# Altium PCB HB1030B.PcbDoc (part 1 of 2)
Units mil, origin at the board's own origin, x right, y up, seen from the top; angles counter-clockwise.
Board outline 1259.84 x 2086.61 mil, 2 copper layers (Top Layer, Bottom Layer); 36 components, 40 nets, 161 pads, 288 vias.
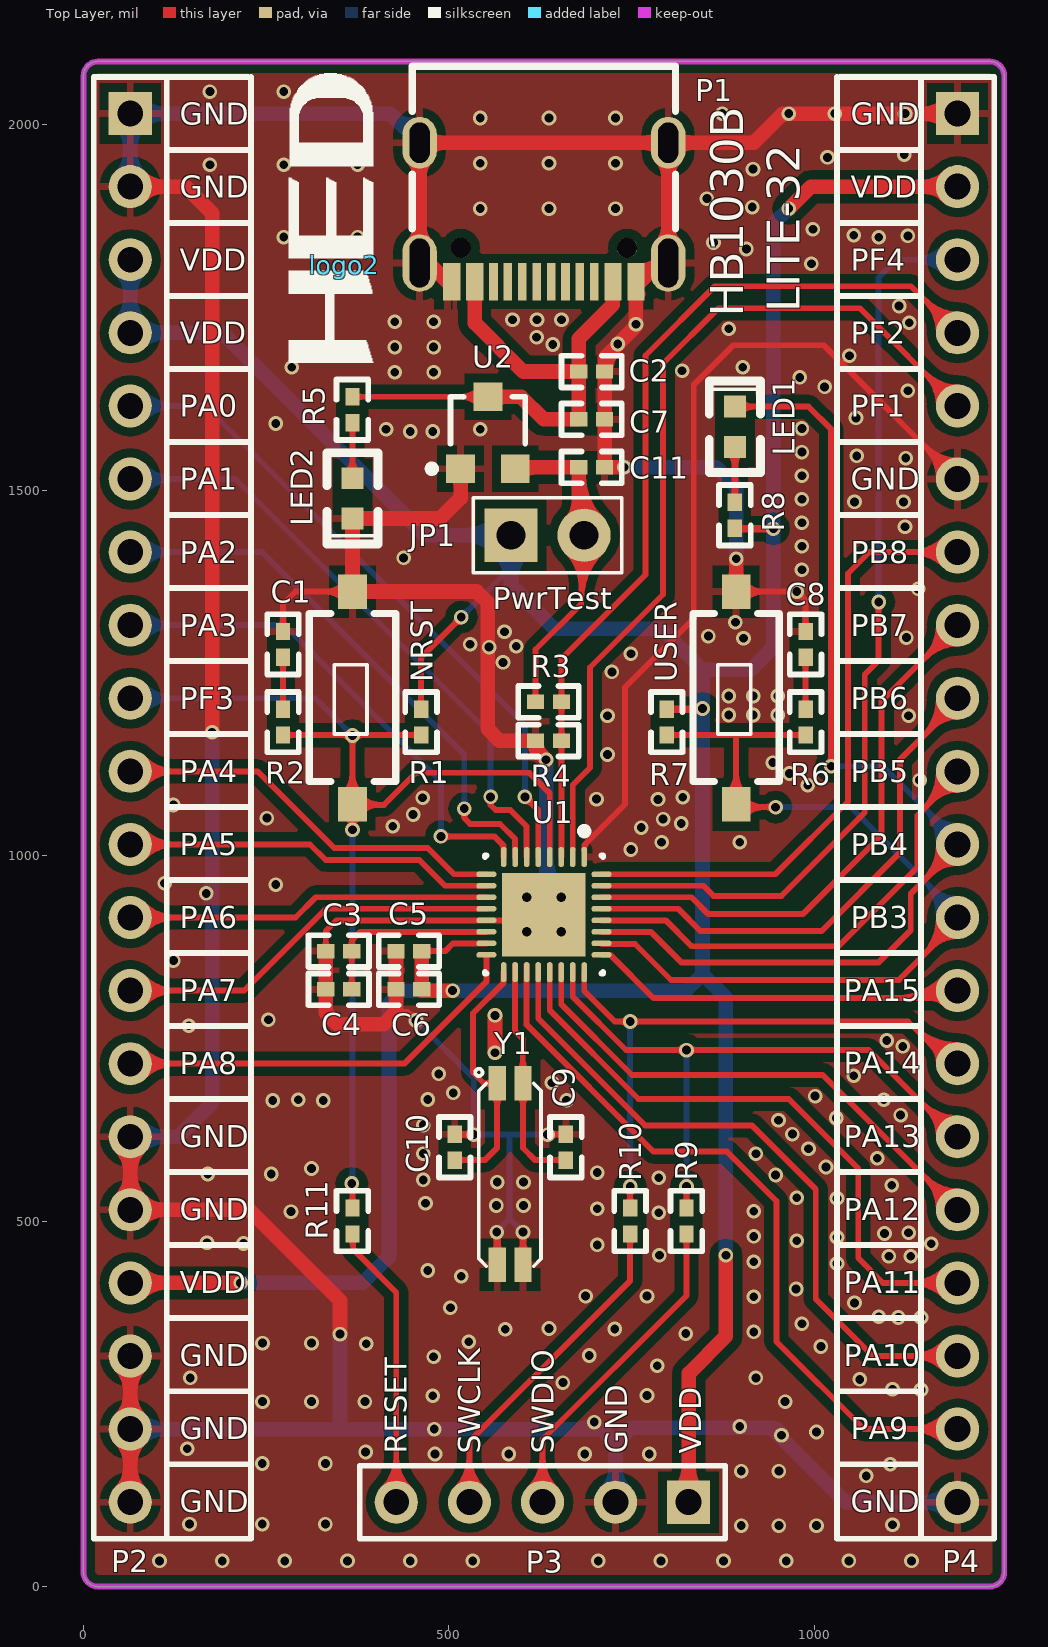
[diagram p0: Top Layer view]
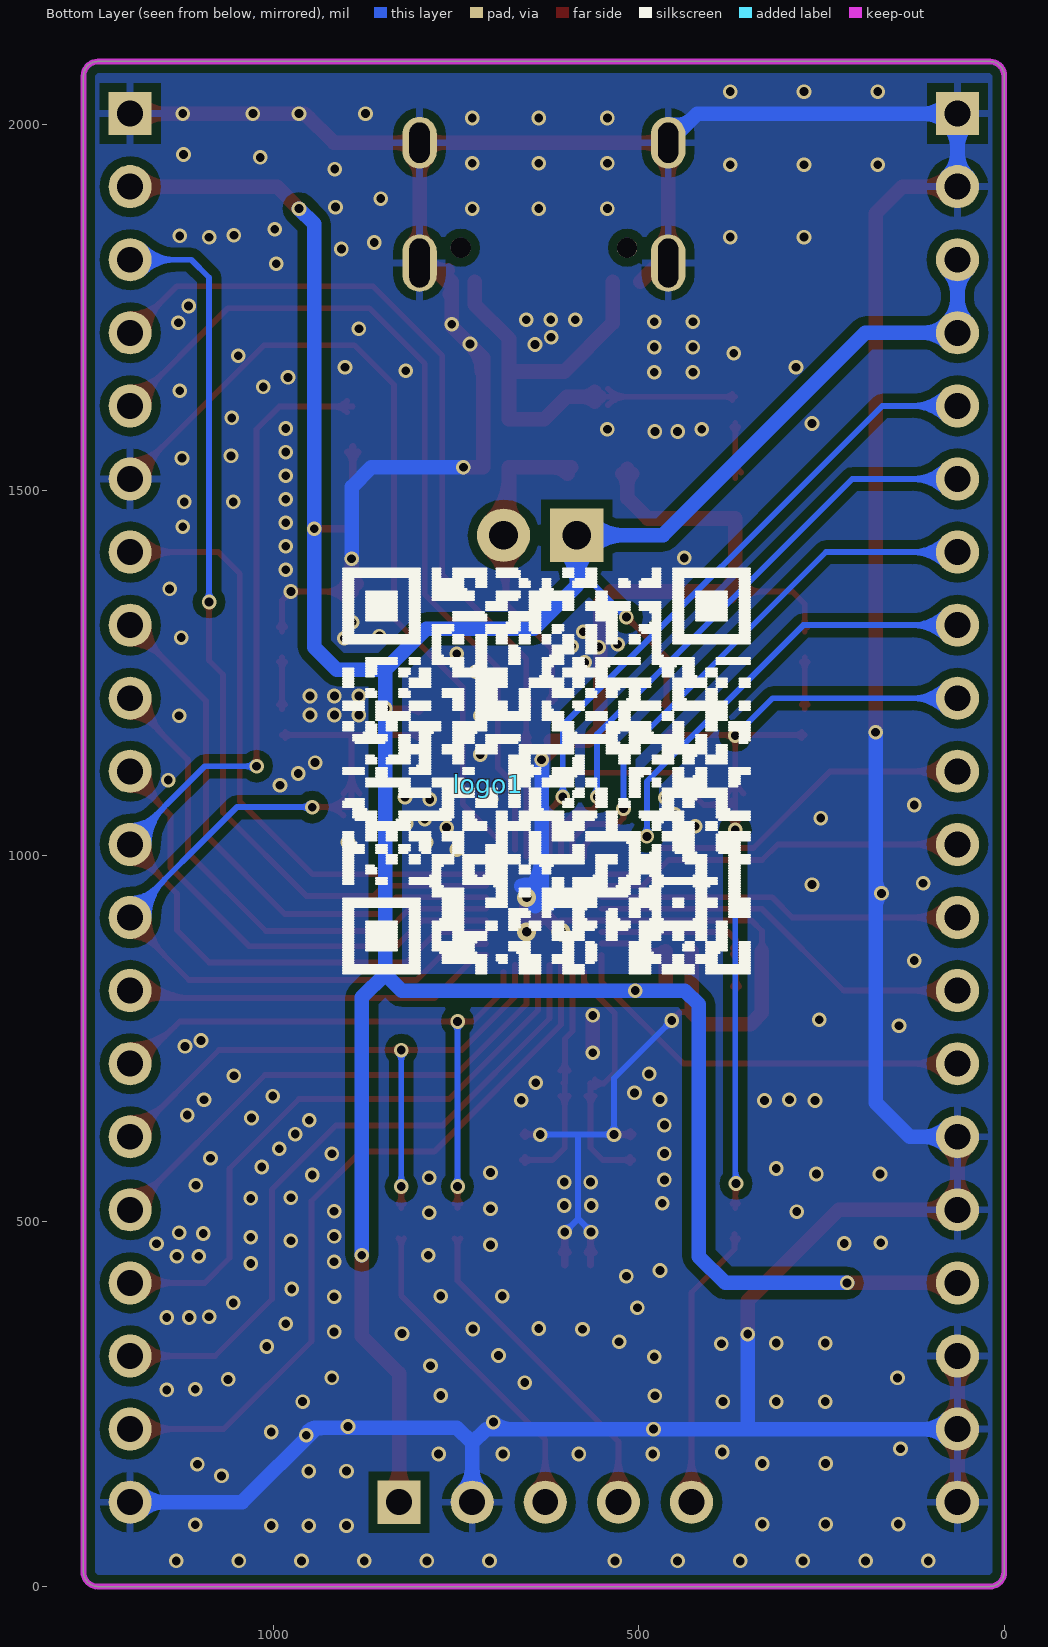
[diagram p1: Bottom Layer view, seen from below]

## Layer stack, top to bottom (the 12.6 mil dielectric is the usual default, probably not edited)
Top Layer: signal copper 1.4
Dielectric: dielectric 12.6, FR-4, Dk 4.8
Bottom Layer: signal copper 1.4

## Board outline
0,19.68 0,2066.93 cw(c19.69,2066.93) 19.69,2086.61 1240.16,2086.61 cw(c1240.16,2066.93) 1259.84,2066.93 1259.84,19.68 cw(c1240.16,19.68) 1240.16,0 19.69,0 cw(c19.69,19.68)

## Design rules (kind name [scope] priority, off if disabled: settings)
Clearance [(IsPad and InComponent('U1'))] p1: gap=7
Clearance Clearance_poly [(InPolygon)] p2: gap=12
Clearance Clearance_CN [(IsPad and InComponent('P1'))] p3: gap=7
Clearance Clearance_Pad [All] p4: gap=7
ComponentClearance [All] p1: gap=0 collisioncheckmode=3 verticalgap=0 showdistances=FALSE
HoleSize [All] p1: absolutevalues=TRUE maxlimit=130 minlimit=1 maxpercent=80.000 minpercent=20.000
MinimumSolderMaskSliver [All] p1: minsoldermaskwidth=0
PolygonConnect PolygonConnect_Pads [IsPad] p1: connectstyle=Relief reliefconductorwidth=10 reliefentries=4 polygonreliefangle="90 Angle"
PolygonConnect [All] p2: connectstyle=Direct reliefconductorwidth=10 reliefentries=4 polygonreliefangle="90 Angle"
RoutingVias [All] p1: holewidth=12 width=20 viastyle="Through Hole" minholewidth=10 minwidth=18 maxholewidth=300 maxwidth=500
SilkToSilkClearance [All] p1: silktosilkclearance=0
SilkscreenOverComponentPads [IsPad] p1: minsilkscreentomaskgap=0
SolderMaskExpansion [All] p1: expansion=4
TestPointUsage [All] p1: valid=0 allowmultiple=FALSE
Testpoint [(IsPad And (OnTopLayer Or OnBottomLayer))] p1: side=3 testpointundercomponent=TRUE minsize=40 maxsize=100 preferedsize=60 minholesize=0 maxholesize=40 preferedholesize=32 testpointgrid=1 style=297 order=0123456789
Width [All] p1: maxlimit=20 minlimit=8 preferedwidth=8
19 further rules are at their usual default settings.

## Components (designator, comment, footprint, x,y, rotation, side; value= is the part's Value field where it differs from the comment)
C1 "0.1u" 0402 273,1271.37 r90 top
C2 "0.1u" 0402 713,1662.37 r180 top
C3 "0.1u" 0402 367,869.37 r180 top
C4 "1u" 0402 367,816.97 r180 top
C5 "0.1u" 0402 427.57,869.37 r0 top
C6 "4.7u" 0402 427.57,816.97 r0 top
C7 "10u" 0402 713,1596.87 r180 top
C8 "0.1u" 0402 988,1306.81 r270 top
C9 "10p" 0402 660,618.81 r270 top
C10 "10p" 0402 508,618.81 r270 top
C11 "10u" 0402 713,1531.28 r180 top
JP1 "Header 1x2" HEADER_1X2_2.54 635,1438.37 r0 top (schematic designator JP2)
LED1 "LED_G" 0603-P 891.35,1559.37 r90 top
LED2 "LED_R" 0603-P 368,1516.37 r270 top
logo1 "SIGN" SIGN 706,1098.37 r180 bottom
logo2 "logo" LOGO 357,1808.37 r90 top
NRST "TS-1101-C-W" 按键_TS-1101-C-W 368,1361.37 r270 top locked
P1 "TYPE-C-16P" HED-KH-TYPE-C-16P 800,1810.82 r0 top locked
P2 "Header 20" HDR1X20 64,2015.37 r270 top locked
P3 "Header 1x5" HDR1X5_2.54 828,115.37 r180 top locked
P4 "Header 20" HDR1X20 1196,2015.37 r270 top locked
R1 "10k" 0402 462,1200.37 r270 top
R2 "10R" 0402 273,1164.94 r90 top
R3 "20K" 0402 654,1210.37 r180 top
R4 "10K" 0402 654,1157.37 r180 top
R5 "1K" 0402 368,1592.37 r90 top
R6 "10R" 0402 988,1200.37 r270 top
R7 "4.7k" 0402 798,1164.94 r90 top
R8 "510R" 0402 891.35,1483.37 r270 top
R9 "470R" 0402 825,517.81 r270 top
R10 "470R" 0402 748,517.81 r270 top
R11 "470R" 0402 368,517.81 r270 top
U1 "CIU32L030K8U6" CIU32L030-QFN32 630,919.37 r270 top locked
U2 "ME6210A33M3G" SOT-23-3 551,1574.37 r0 top locked
USER "TS-1101-C-W" 按键_TS-1101-C-W 893,1361.37 r270 top locked
Y1 "M6-32.768KHz 12.5pF" XTAL-MC146 566,688.37 r270 top

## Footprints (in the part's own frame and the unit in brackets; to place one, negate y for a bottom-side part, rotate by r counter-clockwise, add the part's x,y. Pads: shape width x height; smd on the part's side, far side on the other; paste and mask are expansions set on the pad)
0402 [mm]
  rect 0.6x0.5 smd: 1(0,0) 2(0.9,0)
  silkscreen extent -0.6,-0.55 1.5,0.55
0603-P [mil]
  rect 30x30 smd: 1(0,0) 2(55,0)
  silkscreen extent -35,-35 90,35, body extent 1,-15 60,15, height 10
CIU32L030-QFN32 [mm] "QFN, 32-Leads, Body 4.1x4.1mm (max), Pitch 0.40mm, IPC Medium Density"
  oval 0.7x0.2 smd: 1(-2,1.4) 2(-2,1) 3(-2,0.6) 4(-2,0.2) 5(-2,-0.2) 6(-2,-0.6) 7(-2,-1) 8(-2,-1.4) 17(2,-1.4) 18(2,-1) 19(2,-0.6) 20(2,-0.2) 21(2,0.2) 22(2,0.6) 23(2,1) 24(2,1.4)
  oval 0.2x0.7 smd: 9(-1.4,-2) 10(-1,-2) 11(-0.6,-2) 12(-0.2,-2) 13(0.2,-2) 14(0.6,-2) 15(1,-2) 16(1.4,-2) 25(1.4,2) 26(1,2) 27(0.6,2) 28(0.2,2) 29(-0.2,2) 30(-0.6,2) 31(-1,2) 32(-1.4,2)
  rect 2.9x2.9 smd: 33(0,0)
  silkscreen extent -3.02,-2.05 2.05,2.05, body extent -2.05,-2.05 2.05,2.05, height 0.8
HDR1X5_2.54 [mm]
  rect 1.5x1.5 hole 0.9: 1(0,0)
  round 1.5 hole 0.9: 2(2.54,0) 3(5.08,0) 4(7.62,0) 5(10.16,0)
  silkscreen extent -1.27,-1.27 11.43,1.27
HDR1X20 [mm] "Connector; Header; 20 Position"
  rect 1.5x1.5 hole 0.9: 1(0,0)
  round 1.5 hole 0.9: 2(2.54,0) 3(5.08,0) 4(7.62,0) 5(10.16,0) 6(12.7,0) 7(15.24,0) 8(17.78,0) 9(20.32,0) 10(22.86,0) 11(25.4,0) 12(27.94,0) 13(30.48,0) 14(33.02,0) 15(35.56,0) 16(38.1,0) 17(40.64,0) 18(43.18,0) 19(45.72,0) 20(48.26,0)
  silkscreen extent -1.27,-1.27 49.53,1.27
HEADER_1X2_2.54 [mm]
  rect 1.85x1.85 / inner round 1.85 / far side rect 1.85x1.85 hole 1: 1(-1.27,0)
  round 1.85 hole 1: 2(1.27,0)
  silkscreen extent -2.58,-1.3 2.58,1.3, body extent -2.67,-1.3 2.58,1.3, height 8.38
HED-KH-TYPE-C-16P [mm]
  oval 1.2x2 hole 0.7 slot 1.7 at 90 deg: 1(0,0) 2(-8.64,0)
  oval 1.2x1.8 hole 0.7 slot 1.4 at 90 deg: 3(0,4.18) 4(-8.64,4.18)
  rect 0.3x1.3 smd: A1(-0.97,-0.65) A4(-1.77,-0.65) A5(-3.07,-0.65) A6(-4.07,-0.65) A7(-4.57,-0.65) A8(-5.57,-0.65) A9(-6.87,-0.65) A12(-7.67,-0.65) B1(-7.37,-0.65) B4(-6.57,-0.65) B5(-6.07,-0.65) B6(-5.07,-0.65) B7(-3.57,-0.65) B8(-2.57,-0.65) B9(-2.07,-0.65) B12(-1.27,-0.65)
  round 0.7 hole 0.7 unplated: ""(-7.21,0.53) ""(-1.43,0.53)
  silkscreen extent -8.89,1.19 0.25,6.84
LOGO [mil]
  silkscreen extent -134,-39 262,75
SIGN [mil]
  silkscreen extent -199,-259 358,294
SOT-23-3 [mm]
  rect 1x1 smd: 1(-0.889,-1.143) 2(1.011,-1.143) 3(0.061,1.357)
  silkscreen extent -2.01,-1.27 1.36,1.36, body extent -1.39,-1.29 1.51,1.51, height 1.2
XTAL-MC146 [mm]
  rect 1.2x0.6 smd mask+0.05: 1(0,0) 2(6.3,0) 3(6.3,0.9) 4(0,0.9)
  silkscreen extent -0.51,-0.76 6.35,1.52
按键_TS-1101-C-W [mm] "星坤品牌"
  rect 1.2x1 smd mask+0.05: 1(0,0) 2(7.4,0)
  silkscreen extent 0.76,-1.5 6.6,1.5

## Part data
C1 C3 C4 C5 C6: library part MCD-00211, "Capacitor, MLCC, 100nF, 16V, X7R, 10%, 0603, T=0,8mm"
C2: library part "0603 100nF 10% 50V", "贴片电容"
C7 C11: library part MCD-00014, "Capacitor, MLCC, 10uF, 25V, X5R, 10%, 0805, T=0,85mm"
C8: library part MCD-00211, "贴片电容"
C9 C10: library part Capacitor, "Capacitor, MLCC, 100nF, 16V, X7R, 10%, 0603, T=0,8mm"
JP1: library part MCD-00683, "Header, 2x1, 2,54mm, VR, TH, Height 5.84mm/2.54mm - Shunt Fitted by default"
LED1: library part LED1, "贴片LED 绿色"
LED2: library part LED1, "贴片LED 红色"
NRST: library part SW-PB, "Switch"
P1: library part KH-TYPE-C-16P, "TYPE-C USB接口"
P2 P4: "Header, 20-Pin"
P3: library part SWD, "Header, 1x5, 2,54mm, VR, TH, Height 5.84mm/2.54mm"
R1 R2 R3 R4 R5 R6 R7 R8 R9 R10 R11: library part Res2, "贴片电阻"
U2: library part ME6210, "贴片LDO3.3V"
USER: library part SW-PB, "贴片按键"
Y1: library part MC146, "贴片晶振"

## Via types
v1: diameter 20, hole 12, Top Layer to Bottom Layer, tented both sides, 284 vias
v2: diameter 25.98, hole 12.99, Top Layer to Bottom Layer, tented top, 4 vias

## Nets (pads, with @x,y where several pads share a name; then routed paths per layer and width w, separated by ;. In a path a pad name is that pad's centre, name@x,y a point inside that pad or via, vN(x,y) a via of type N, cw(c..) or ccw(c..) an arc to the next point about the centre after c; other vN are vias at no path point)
GND: C1.2 C2.1 C3.2 C4.2 C5.1 C6.1 C7.1 C8.1 C9.1 C10.1 C11.1 LED2.2 NRST.1 P1.1 P1.2 P1.3 P1.4 P1.A1 P1.A12 P1.B1 P1.B12 P2.1 P2.2 P2.15 P2.16 P2.18 P2.19 P2.20 P3.2 P4.1 P4.6 P4.20 R4.2 U1.1 U1.13 U1.33 U2.1 USER.1 Y1.2 Y1.3 | length 16114.8
  Top Layer w8: C1.2@273,1306.81 273,1344.37 290,1361.37 NRST.1@368,1361.37 ; C3.2@331.57,869.37 331.57,896.94 346.13,911.5 U1.13@551.26,911.5 U1.33@606.38,911.5 ; C6.1@427,815.37 C6.1@427.57,815.94 ; 427.57,785.94 443.43,785.94 v1(455,774.37) ; R4.2@618.57,1155.6 R4.2@618.57,1157.37 ; U1.33@622.13,921.5 U1.33@630,929.37 ; v1(635,618.37) C9.1@659.57,618.37 ; U1.1@685.12,1008.11 685.12,1014.49 741,1070.37 741,1230.37 835,1324.37 835,1644.37 889,1698.37 1013,1698.37 P4.6@1196,1515.37 ; USER.1@893,1361.37 v1(976,1361.37) 988,1349.37 C8.1@988,1306.81 ; 273,1322.88 cw(c258.9,1322.88) 268.87,1312.91 ccw(c258.9,1322.88) 273,1322.88 ; 273,1322.88 ccw(c287.1,1322.88) 277.13,1312.91 cw(c287.1,1322.88) 273,1322.88 ; 330.13,1361.37 cw(c330.13,1323.51) 356.91,1350.28 ccw(c330.13,1323.51) 330.13,1361.37 ; 330.13,1361.37 ccw(c330.13,1399.24) 356.91,1372.46 cw(c330.13,1399.24) 330.13,1361.37 ; 331.57,883.48 cw(c317.46,883.48) 327.44,873.51 ccw(c317.46,883.48) 331.57,883.48 ; 331.57,883.48 ccw(c345.67,883.48) 335.7,873.51 cw(c345.67,883.48) 331.57,883.48 ; 444.76,784.62 cw(c434.51,774.37) 449,774.37 ccw(c434.51,774.37) 444.76,784.62 ; 444.76,784.62 ccw(c455,794.86) 455,780.37 cw(c455,794.86) 444.76,784.62 ; 649.49,618.37 cw(c649.49,632.86) 639.24,622.62 ccw(c649.49,632.86) 649.49,618.37 ; 649.49,618.37 ccw(c649.49,603.89) 639.24,614.13 cw(c649.49,603.89) 649.49,618.37 ; 930.87,1361.37 cw(c930.87,1399.24) 904.09,1372.46 ccw(c930.87,1399.24) 930.87,1361.37 ; 930.87,1361.37 ccw(c930.87,1323.51) 904.09,1350.28 cw(c930.87,1323.51) 930.87,1361.37 ; 961.51,1361.37 cw(c961.51,1346.89) 971.76,1357.13 ccw(c961.51,1346.89) 961.51,1361.37 ; 961.51,1361.37 ccw(c961.51,1375.86) 971.76,1365.62 cw(c961.51,1375.86) 961.51,1361.37 ; 986.24,1351.13 cw(c996.49,1361.37) 982,1361.37 ccw(c996.49,1361.37) 986.24,1351.13 ; 986.24,1351.13 ccw(c976,1340.89) 976,1355.37 cw(c976,1340.89) 986.24,1351.13 ; 988,1322.88 cw(c973.9,1322.88) 983.87,1312.91 ccw(c973.9,1322.88) 988,1322.88 ; 988,1322.88 ccw(c1002.1,1322.88) 992.13,1312.91 cw(c1002.1,1322.88) 988,1322.88 ; 1152.42,1558.95 cw(c1108.84,1515.37) 1170.47,1515.37 ccw(c1108.84,1515.37) 1152.42,1558.95 ; 1152.42,1558.95 ccw(c1196,1602.53) 1196,1540.9 cw(c1196,1602.53) 1152.42,1558.95 ; 1166.08,1545.3 cw(c1136.16,1515.37) 1178.47,1515.37 ccw(c1136.16,1515.37) 1166.08,1545.3 ; 1166.08,1545.3 ccw(c1196,1575.22) 1196,1532.9 cw(c1196,1575.22) 1166.08,1545.3 ; v1@644.85,618.37 ccw(c644.85,633.96) 655.87,622.94 cw(c644.85,633.96) v1@644.85,618.37 ; 646.94,618.37 cw(c646.94,605.75) 655.87,614.68 ccw(c646.94,605.75) 646.94,618.37 ; U1.1@685.06,1007.96 cw(c700.68,1007.96) 689.63,1019.01 ccw(c700.68,1007.96) U1.1@685.06,1007.96
  Top Layer w10: P2.15@59,615.37 P2.15@64,615.37 ; P1.2@451.45,1810.82 P1.2@459.84,1810.82 ; C10.1@508,618.81 508.43,618.37 v1(534,618.37) ; v1(565.43,484.94) 566,484.37 Y1.2@566,440.34 ; Y1.3@601.43,440.34 v1(601.43,484.94) ; v1@635,619.37 v1@635.57,618.81 ; 521.93,618.37 cw(c521.93,606.3) 530.46,614.84 ccw(c521.93,606.3) 521.93,618.37 ; 521.93,618.37 ccw(c521.93,630.45) 530.46,621.91 cw(c521.93,630.45) 521.93,618.37 ; 566,468.6 cw(c549.56,468.6) 561.18,456.97 ccw(c549.56,468.6) 566,468.6 ; 566,468.6 ccw(c582.44,468.6) 570.82,456.97 cw(c582.44,468.6) 566,468.6 ; 601.43,468.6 cw(c584.99,468.6) 596.62,456.97 ccw(c584.99,468.6) 601.43,468.6 ; 601.43,468.6 ccw(c617.88,468.6) 606.25,456.97 cw(c617.88,468.6) 601.43,468.6 ; 601.43,472.87 cw(c613.5,472.87) 604.97,481.41 ccw(c613.5,472.87) 601.43,472.87 ; 601.43,472.87 ccw(c589.36,472.87) 597.9,481.41 cw(c589.36,472.87) 601.43,472.87 ; C10.1@511.42,615.38 cw(c518.65,608.16) 518.65,618.37 ccw(c518.65,608.16) C10.1@511.42,615.38 ; C10.1@511.42,622.23 ccw(c520.74,631.54) 520.74,618.37 cw(c520.74,631.54) C10.1@511.42,622.23 ; v1@561.9,481.41 cw(c551.99,471.5) 566,471.5 ccw(c551.99,471.5) v1@561.9,481.41 ; 566,474.24 cw(c576.14,474.24) 568.97,481.41 ccw(c576.14,474.24) 566,474.24
  Top Layer w20: P2.20@64,115.37 P2.19@64,215.37 P2.18@64,315.37 ; P2.15@64,615.37 P2.16@64,515.37 226.63,515.37 351,391 v1(351,345.37) ; P2.2@64,1915.37 139.63,1915.37 176,1879 v1(176,1169) ; C3.2@331.57,869.37 C4.2@331.57,816.97 331.57,784.81 347,769.37 411,769.37 427.57,785.94 C6.1@427.57,815.94 ; C6.1@427.57,816.97 C5.1@427.57,869.37 ; P1.A12@498.03,1785.23 472.43,1810.82 P1.2@459.84,1810.82 P1.4@459.84,1975.39 P1.3@800,1975.39 ; U2.1@516,1529.37 516,1489.37 488,1461.37 LED2.2@368,1461.37 NRST.1@368,1361.37 538,1361.37 553,1346.37 553,1173.37 569,1157.37 R4.2@618.57,1157.37 618.57,1145.81 v1(633,1131.37) ; v1(563,730.37) v1(563,781.37) ; v2(606.38,895.75) v2(653.62,943) v2(653.62,895.75) U1.33@630,919.37 ; C11.1@713,1531.28 C7.1@713,1596.87 C2.1@713,1662.37 713,1681.37 755.81,1724.19 P1.B12@755.81,1785.23 ; C11.1@713.09,1531.37 v1(740,1531.37) ; P1.A1@761.81,1785.23 P1.1@787.41,1810.82 ; USER.1@893,1361.37 v1(893,1406.37) ; P4.1@1196,2015.37 957,2015.37 917.02,1975.39 P1.3@800,1975.39 ; 64,162.52 cw(c16.86,162.52) 50.19,129.18 ccw(c16.86,162.52) 64,162.52 ; 64,162.52 ccw(c111.14,162.52) 77.81,129.18 cw(c111.14,162.52) 64,162.52 ; 64,168.23 cw(c111.14,168.23) 77.81,201.57 ccw(c111.14,168.23) 64,168.23 ; 64,168.23 ccw(c16.86,168.23) 50.19,201.57 cw(c16.86,168.23) 64,168.23 ; 64,262.52 cw(c16.86,262.52) 50.19,229.18 ccw(c16.86,262.52) 64,262.52 ; 64,262.52 ccw(c111.14,262.52) 77.81,229.18 cw(c111.14,262.52) 64,262.52 ; 64,268.23 cw(c111.14,268.23) 77.81,301.57 ccw(c111.14,268.23) 64,268.23 ; 64,268.23 ccw(c16.86,268.23) 50.19,301.57 cw(c16.86,268.23) 64,268.23 ; 64,562.52 cw(c16.86,562.52) 50.19,529.18 ccw(c16.86,562.52) 64,562.52 ; 64,562.52 ccw(c111.14,562.52) P2.16@77.81,529.18 ; 64,562.52 ccw(c111.14,562.52) P2.16@77.81,529.18 ; 64,568.23 cw(c111.14,568.23) 77.81,601.57 ccw(c111.14,568.23) 64,568.23 ; 64,568.23 ccw(c16.86,568.23) 50.19,601.57 cw(c16.86,568.23) 64,568.23 ; P2.16@77.81,529.18 ccw(c111.14,562.52) 111.14,515.37 ; P2.16@77.81,529.18 ccw(c111.14,562.52) 111.14,515.37 ; 111.14,515.37 ccw(c111.14,468.23) 77.81,501.57 cw(c111.14,468.23) 111.14,515.37 ; 111.14,1915.37 cw(c111.14,1962.52) 77.81,1929.18 ccw(c111.14,1962.52) 111.14,1915.37 ; 111.14,1915.37 ccw(c111.14,1868.23) 77.81,1901.57 cw(c111.14,1868.23) 111.14,1915.37 ; 368,1388.69 cw(c344.62,1388.69) 361.15,1372.16 ccw(c344.62,1388.69) 368,1388.69 ; 368,1388.69 ccw(c391.38,1388.69) 374.85,1372.16 cw(c391.38,1388.69) 368,1388.69 ; 391.38,1361.37 cw(c391.38,1384.76) 374.85,1368.22 ccw(c391.38,1384.76) 391.38,1361.37 ; 391.38,1361.37 ccw(c391.38,1337.99) 374.85,1354.53 cw(c391.38,1337.99) 391.38,1361.37 ; 459.84,1859.46 cw(c426.96,1859.46) 450.21,1836.2 ccw(c426.96,1859.46) 459.84,1859.46 ; 459.84,1859.46 ccw(c492.73,1859.46) 469.48,1836.2 cw(c492.73,1859.46) 459.84,1859.46 ; 459.84,1930.69 cw(c492.73,1930.69) 469.48,1953.95 ccw(c492.73,1930.69) 459.84,1930.69 ; 459.84,1930.69 ccw(c426.96,1930.69) 450.21,1953.95 cw(c426.96,1930.69) 459.84,1930.69 ; 492.73,1975.39 cw(c492.73,2008.28) 469.48,1985.02 ccw(c492.73,2008.28) 492.73,1975.39 ; 492.73,1975.39 ccw(c492.73,1942.5) 469.48,1965.76 cw(c492.73,1942.5) 492.73,1975.39 ; 516,1505.99 cw(c539.38,1505.99) 522.85,1522.53 ccw(c539.38,1505.99) 516,1505.99 ; 516,1505.99 ccw(c492.62,1505.99) 509.15,1522.53 cw(c492.62,1505.99) 516,1505.99 ; 767.11,1975.39 cw(c767.11,1942.5) 790.37,1965.76 ccw(c767.11,1942.5) 767.11,1975.39 ; 767.11,1975.39 ccw(c767.11,2008.28) 790.37,1985.02 cw(c767.11,2008.28) 767.11,1975.39 ; P1.1@787.41,1810.82 cw(c763.18,1835.06) 761.63,1800.82 ccw(c763.18,1835.06) P1.1@787.41,1810.82 ; P1.1@787.41,1810.82 P1.1@800,1810.82 P1.3@800,1975.39 ; 800,1859.46 cw(c767.11,1859.46) 790.37,1836.2 ccw(c767.11,1859.46) 800,1859.46 ; 800,1859.46 ccw(c832.89,1859.46) 809.63,1836.2 cw(c832.89,1859.46) 800,1859.46 ; 800,1930.69 cw(c832.89,1930.69) 809.63,1953.95 ccw(c832.89,1930.69) 800,1930.69 ; 800,1930.69 ccw(c767.11,1930.69) 790.37,1953.95 cw(c767.11,1930.69) 800,1930.69 ; 832.89,1975.39 cw(c832.89,2008.28) 809.63,1985.02 ccw(c832.89,2008.28) 832.89,1975.39 ; 832.89,1975.39 ccw(c832.89,1942.5) 809.63,1965.76 cw(c832.89,1942.5) 832.89,1975.39 ; 893,1388.69 cw(c869.62,1388.69) 886.15,1372.16 ccw(c869.62,1388.69) 893,1388.69 ; 893,1388.69 ccw(c916.38,1388.69) 899.85,1372.16 cw(c916.38,1388.69) 893,1388.69 ; 1148.86,2015.37 cw(c1148.86,1968.23) 1182.19,2001.57 ccw(c1148.86,1968.23) 1148.86,2015.37 ; 1148.86,2015.37 ccw(c1148.86,2062.52) 1182.19,2029.18 cw(c1148.86,2062.52) 1148.86,2015.37 ; P1.2@451.31,1820.04 cw(c456.18,1805.8) 466.82,1816.44 ccw(c456.18,1805.8) P1.2@451.31,1820.04 ; P1.2@457.78,1801.11 cw(c467.74,1771.98) 489.51,1793.75 ccw(c467.74,1771.98) P1.2@457.78,1801.11 ; R4.2@620.38,1157.4 ccw(c641.34,1153.25) 626.23,1138.14 cw(c641.34,1153.25) R4.2@620.38,1157.4 ; C2.1@714.81,1662.37 cw(c765.05,1662.37) 729.53,1697.9 ccw(c765.05,1662.37) C2.1@714.81,1662.37 ; P1.B12@755.81,1760.94 cw(c766.41,1760.94) 758.92,1768.44 ccw(c766.41,1760.94) P1.B12@755.81,1760.94 ; P1.B12@755.81,1780.63 cw(c766.41,1780.63) 758.92,1788.12 ccw(c766.41,1780.63) P1.B12@755.81,1780.63 ; 770.33,1793.75 cw(c792.11,1771.98) 802.06,1801.11 ccw(c792.11,1771.98) 770.33,1793.75 ; P1.1@793.02,1816.44 cw(c803.66,1805.8) 808.53,1820.04 ccw(c803.66,1805.8) P1.1@793.02,1816.44 ; 951.34,2009.72 cw(c965,1996.06) v1(965,2015.37) ccw(c965,1996.06) 951.34,2009.72
  Bottom Layer w8: v1(455,774.37) 534,695.37 v1(534,618.37) 583,618.37 ; v1(565.43,484.94) 565.43,485.81 583,503.37 ; v1(601.43,484.94) 583,503.37 ; v1(635,618.37) 583,618.37 ; P3.2@728,103.37 P3.2@728,115.37 728,194.37 ; 465.24,764.13 cw(c475.49,774.37) 461,774.37 ccw(c475.49,774.37) 465.24,764.13 ; 465.24,764.13 ccw(c455,753.89) 455,768.37 cw(c455,753.89) 465.24,764.13 ; 534,632.86 cw(c519.51,632.86) 529.76,622.62 ccw(c519.51,632.86) 534,632.86 ; 534,632.86 ccw(c548.49,632.86) v1@538.24,622.62 ; 534,632.86 ccw(c548.49,632.86) v1@538.24,622.62 ; v1@538.24,622.62 ccw(c548.49,632.86) 548.49,618.37 ; v1@538.24,622.62 ccw(c548.49,632.86) 548.49,618.37 ; 548.49,618.37 ccw(c548.49,603.89) 538.24,614.13 cw(c548.49,603.89) 548.49,618.37 ; 583,503.37 583,618.37 ; 591.19,495.18 cw(c580.95,484.94) 595.43,484.94 ccw(c580.95,484.94) 591.19,495.18 ; 591.19,495.18 ccw(c601.43,505.43) 601.43,490.94 cw(c601.43,505.43) 591.19,495.18 ; 620.51,618.37 cw(c620.51,603.89) 630.76,614.13 ccw(c620.51,603.89) 620.51,618.37 ; 620.51,618.37 ccw(c620.51,632.86) 630.76,622.62 cw(c620.51,632.86) 620.51,618.37 ; 728,157.69 cw(c685.68,157.69) 715.61,127.77 ccw(c685.68,157.69) 728,157.69 ; 728,157.69 ccw(c770.32,157.69) 740.39,127.77 cw(c770.32,157.69) 728,157.69 ; 728,177 cw(c666.37,177) 709.95,133.42 ccw(c666.37,177) 728,177 ; 728,177 ccw(c789.63,177) 746.05,133.42 cw(c789.63,177) 728,177 ; v1@565.43,490.94 ccw(c565.43,503.33) 574.2,494.57 cw(c565.43,503.33) v1@565.43,490.94 ; v1@571.43,484.94 cw(c588.01,484.94) 576.29,496.66 ccw(c588.01,484.94) v1@571.43,484.94
  Bottom Layer w20: P2.19@64,215.37 709,215.37 728,196.37 ; P2.15@64,615.37 129.37,615.37 176,662 v1(176,1169) ; P2.2@64,1915.37 P2.1@64,2015.37 419.86,2015.37 P1.4@459.84,1975.39 ; 351,215.37 v1(351,345.37) ; v1@633,1130.37 633,947 ; v2(653.62,943) 629,943 633,947 ; P3.2@728,115.37 728,196.37 ; v1(740,1531.37) 866,1531.37 893,1504.37 v1(893,1406.37) ; P4.20@1196,115.37 1043,115.37 941,217.37 ; 64,1962.52 cw(c16.86,1962.52) 50.19,1929.18 ccw(c16.86,1962.52) 64,1962.52 ; 64,1962.52 ccw(c111.14,1962.52) 77.81,1929.18 cw(c111.14,1962.52) 64,1962.52 ; 64,1968.23 cw(c111.14,1968.23) P2.1@77.81,2001.57 ; 64,1968.23 ccw(c16.86,1968.23) 50.19,2001.57 cw(c16.86,1968.23) 64,1968.23 ; 64,1968.23 cw(c111.14,1968.23) P2.1@77.81,2001.57 ; P2.1@77.81,2001.57 cw(c111.14,1968.23) 111.14,2015.37 ; P2.1@77.81,2001.57 cw(c111.14,1968.23) 111.14,2015.37 ; 111.14,215.37 cw(c111.14,262.52) 77.81,229.18 ccw(c111.14,262.52) 111.14,215.37 ; 111.14,215.37 ccw(c111.14,168.23) 77.81,201.57 cw(c111.14,168.23) 111.14,215.37 ; 111.14,615.37 cw(c111.14,662.52) 77.81,629.18 ccw(c111.14,662.52) 111.14,615.37 ; 111.14,615.37 ccw(c111.14,568.23) 77.81,601.57 cw(c111.14,568.23) 111.14,615.37 ; 111.14,2015.37 cw(c111.14,2062.52) 77.81,2029.18 ccw(c111.14,2062.52) 111.14,2015.37 ; v1(168,948.37) cw(c148.69,929.06) 176,929.06 ccw(c148.69,929.06) v1(168,948.37) ; v1(168,948.37) ccw(c148.69,967.69) 176,967.69 cw(c148.69,967.69) v1(168,948.37) ; 633,947 cw(c619.67,960.32) 608.2,945.37 ccw(c619.67,960.32) 633,947 ; 728,162.52 cw(c680.86,162.52) 714.19,129.18 ccw(c680.86,162.52) 728,162.52 ; 728,162.52 ccw(c775.14,162.52) 741.81,129.18 cw(c775.14,162.52) 728,162.52 ; 728,196.37 749,217.37 941,217.37 ; 941,217.37 cw(c941,202.74) v1(955,207) ; 941,217.37 cw(c941,202.74) v1(955,207) ; v1(955,207) ccw(c929.95,181.95) 929.95,217.37 cw(c929.95,181.95) v1(955,207) ; 1148.86,115.37 cw(c1148.86,68.23) 1182.19,101.57 ccw(c1148.86,68.23) 1148.86,115.37 ; 1148.86,115.37 ccw(c1148.86,162.52) 1182.19,129.18 cw(c1148.86,162.52) 1148.86,115.37 ; 425.77,2009.47 ccw(c449.44,2033.14) 456.84,2000.49 cw(c449.44,2033.14) 425.77,2009.47 ; 620.69,934.69 cw(c640.53,914.85) 652.36,940.28 ccw(c640.53,914.85) 620.69,934.69 ; 633,951.72 ccw(c662.35,951.72) 641.6,930.97 cw(c662.35,951.72) 633,951.72 ; 633,1000.01 ccw(c710.63,1000.01) 655.74,945.11 cw(c710.63,1000.01) 633,1000.01 ; 640.83,954.82 cw(c653.41,942.24) 658.23,959.37 ccw(c653.41,942.24) 640.83,954.82 ; 640.9,954.9 cw(c653.36,942.44) 660.8,958.42 ccw(c653.36,942.44) 640.9,954.9 ; 675.76,215.37 ccw(c675.76,248.24) v1(699,225) cw(c675.76,248.24) 675.76,215.37
  other v1: 104,35 189.75,35 275.5,35 361.25,35 447,35 532.75,35 704.25,35 790,35 875.75,35 961.5,35 1047.25,35 1133,35 900,83.37 951.5,83.37 1003,83.37 1107,84.37 145,85.37 244.5,85.37 331,85.37 1071,151.37 900,157.87 951.5,157.87 1104,167.37 244.5,168.25 331,168.25 481,181.37 582,181.37 686,181.37 774,181.37 386,184 142,188.37 1003,211.37 480,215.37 898,219 245,253 312,253 385,253 960,253 478,261 771,261.37 1146,269 1107,270 656,279 1062,283.37 146,285.37 920,285.37 785,302 479,314.37 692,316 1009,328.37 387,332 245,333 312,333 527,335 824,346 917,348.37 577,352 727,352.37 637,353 983,359.37 1115,368 1146,368 1088,369 502,381.37 1055,388 917,396.37 687,397.37 771,397.37 975,407 517,424.37 471,432.37 1031,442 917,444.37 1102,452 1132,452 788,453.37 703,467.37 219,469.37 1160,469 169,470.37 976,473 1031,478 917,479 1096,483 1129,484 787,511.37 284,513 917,513.37 703,516.87 565,521.37 602,521.37 468,524.37 1031,531 976,532 1106,549 566,553.37 602,553.37 465,556.37 787,559.37 947,563 170,564.37 257,564.37 703,566.37 312,572 1016,574 1086,586 465,592.37 920,592 992,599 970,619 465,631.37 951,638 1030,641 1118,645 259,665 328,665 661,665.37 294,666 471,666.37 1095,666 1001,671 506,675.37 641,689.37 1054,699 486,701.37 1121,739 1099,747 144,767.37 253,775.37 123,856.37 263,960.37 111,962.37 749,1008.37 791,1018.37 898,1018.37 763,1038.37 423,1040.37 818,1044 793,1050 251,1051.37 451,1056.37 123,1069.37 702,1077.37 786,1077 464,1079.37 820,1080 991,1096.37 1144,1103.37 966,1112.37 943,1127.37 717,1138.37 717,1191.37 1129,1191.37 883,1192.37 916.5,1192.37 950,1192.37 883,1218.37 916.5,1218.37 950,1218.37 723,1251.37 574,1264.37 749,1276.37 555,1285.37 592,1286.37 529,1289.37 903,1297.37 1126,1298.37 855,1300.37 576,1306.37 892,1319.37 1142,1365 983,1391.04 438,1407.37 983,1423.26 1124,1450 983,1455.48 1055,1484 1122,1484 983,1487.71 983,1519.93 1125,1544 1058,1547 983,1552.15 447,1580.37 478,1580.37 414,1583.37 543,1583.37 983,1584.37 263,1591.37 1057,1599 1128,1636 1014,1641.37 980,1654.37 426,1661.37 479,1661.37 819,1663.37 285,1668.37 902,1668.37 1048,1684 370,1687.37 426,1695.87 479,1695.87 642,1699.37 731,1700 620,1709.37 883,1721 756,1727 1130,1729 426,1730.37 479,1730.37 587,1733.37 620.5,1733.37 654,1733.37 1116,1752 996,1810 907,1830 862,1839 274,1846.37 375,1846.37 1088,1846 1128,1848 1054,1849 998,1857 543,1885.37 637,1885.37 728,1885.37 915,1887.37 853,1899 916,1939.37 173,1945.37 274,1945.37 375,1945.37 543,1947.37 637,1947.37 728,1947.37 1018,1955.37 1123,1959.37 543,2009.37 637,2009.37 728,2009.37 874,2015.37 1028,2015.37 1124,2015.37 173,2045.37 274,2045.37 375,2045.37
  other v2: 606.38,943
LXTAL_IN: C9.2 U1.18 Y1.4 | length 483.4
  Top Layer w8: U1.18@590.63,850.63 U1.18@590.63,840.63 590.63,759.74 601,749.37 Y1.4@601,688.94 ; Y1.4@601.43,688.37 601.43,599.94 618,583.37 C9.2@660,583.37 ; Y1.4@602.43,688.37 Y1.4@603,688.94 ; 601.43,657.71 cw(c620.29,657.71) 606.96,671.04 ccw(c620.29,657.71) 601.43,657.71 ; 601.43,657.71 ccw(c582.58,657.71) 595.91,671.04 cw(c582.58,657.71) 601.43,657.71 ; 645.9,583.37 cw(c645.9,569.27) 655.87,579.24 ccw(c645.9,569.27) 645.9,583.37 ; 645.9,583.37 ccw(c645.9,597.48) 655.87,587.51 cw(c645.9,597.48) 645.9,583.37 ; Y1.4@595.91,705.71 ccw(c583.62,718) 601,718 cw(c583.62,718) Y1.4@595.91,705.71 ; 601,720.09 ccw(c621.34,720.09) 606.96,705.71 cw(c621.34,720.09) 601,720.09
LXTAL_OUT: C10.2 U1.17 Y1.1 | length 523.9
  Top Layer w8: C10.2@508,583.37 549,583.37 566,600.37 Y1.1@566,688.37 548,688.37 ; Y1.1@566,689.37 Y1.1@567,688.37 ; U1.17@574.88,840.63 574.88,826.26 533,784.37 533,703.37 548,688.37 ; 522.1,583.37 cw(c522.1,597.48) 512.13,587.51 ccw(c522.1,597.48) 522.1,583.37 ; 522.1,583.37 ccw(c522.1,569.27) 512.13,579.24 cw(c522.1,569.27) 522.1,583.37 ; 548,688.37 cw(c548,671.54) 560.29,683.04 ccw(c548,671.54) 548,688.37 ; 548,688.37 ccw(c548,705.21) 560.29,693.71 cw(c548,705.21) 548,688.37 ; 566,657.71 cw(c584.86,657.71) 571.52,671.04 ccw(c584.86,657.71) 566,657.71 ; 566,657.71 ccw(c547.14,657.71) 560.48,671.04 cw(c547.14,657.71) 566,657.71 ; 571.78,823.16 ccw(c564.15,830.79) 574.94,830.79 cw(c564.15,830.79) 571.78,823.16
NetC1_1: C1.1 R2.2 | length 159.6
  Top Layer w8: R2.2@273,1200.37 C1.1@273,1271.37 ; 273,1216.45 cw(c258.9,1216.45) 268.87,1206.47 ccw(c258.9,1216.45) 273,1216.45 ; 273,1216.45 ccw(c287.1,1216.45) 277.13,1206.47 cw(c287.1,1216.45) 273,1216.45 ; 273,1255.3 cw(c287.1,1255.3) 277.13,1265.27 ccw(c287.1,1255.3) 273,1255.3 ; 273,1255.3 ccw(c258.9,1255.3) 268.87,1265.27 cw(c258.9,1255.3) 273,1255.3
NetC8_2: C8.2 R6.1 | length 159.6
  Top Layer w8: R6.1@988,1200.37 C8.2@988,1271.37 ; 988,1216.45 cw(c973.9,1216.45) 983.87,1206.47 ccw(c973.9,1216.45) 988,1216.45 ; 988,1216.45 ccw(c1002.1,1216.45) 992.13,1206.47 cw(c1002.1,1216.45) 988,1216.45 ; 988,1255.3 cw(c1002.1,1255.3) 992.13,1265.27 ccw(c1002.1,1255.3) 988,1255.3 ; 988,1255.3 ccw(c973.9,1255.3) 983.87,1265.27 cw(c973.9,1255.3) 988,1255.3
NetLED1_1: LED1.1 R8.1 | length 188.6
  Top Layer w10: R8.1@891.35,1483.37 LED1.1@891.35,1559.37 ; 891.35,1497.03 cw(c879.66,1497.03) 887.92,1488.77 ccw(c879.66,1497.03) 891.35,1497.03 ; 891.35,1497.03 ccw(c903.04,1497.03) 894.77,1488.77 cw(c903.04,1497.03) 891.35,1497.03 ; 891.35,1535.23 cw(c915.49,1535.23) 898.42,1552.3 ccw(c915.49,1535.23) 891.35,1535.23 ; 891.35,1535.23 ccw(c867.2,1535.23) 884.27,1552.3 cw(c867.2,1535.23) 891.35,1535.23
NetLED2_1: LED2.1 R5.1 | length 203.7
  Top Layer w8: LED2.1@368,1516.37 R5.1@368,1592.37 ; 368,1542.93 cw(c341.45,1542.93) 360.22,1524.15 ccw(c341.45,1542.93) 368,1542.93 ; 368,1542.93 ccw(c394.56,1542.93) 375.78,1524.15 cw(c394.56,1542.93) 368,1542.93 ; 368,1576.3 cw(c382.1,1576.3) 372.13,1586.27 ccw(c382.1,1576.3) 368,1576.3 ; 368,1576.3 ccw(c353.9,1576.3) 363.87,1586.27 cw(c353.9,1576.3) 368,1576.3
PA0: P2.5 U1.5 | length 1163.1
  Top Layer w8: v1(604,1080.37) 622.13,1062.25 U1.5@622.13,998.11 ; 614.24,1070.13 cw(c624.49,1080.37) 610,1080.37 ccw(c624.49,1080.37) 614.24,1070.13 ; 614.24,1070.13 ccw(c604,1059.89) 604,1074.37 cw(c604,1059.89) 614.24,1070.13
  Bottom Layer w8: P2.5@64,1615.37 167,1615.37 604,1178.37 v1(604,1080.37) ; P2.5@76.39,1602.98 cw(c106.32,1573.06) 106.32,1615.37 cw(c106.32,1657.69) P2.5@76.39,1627.77 ; P2.5@82.05,1597.32 cw(c125.63,1553.75) 125.63,1615.37 cw(c125.63,1677) P2.5@82.05,1633.42 ; 604,1094.86 cw(c589.51,1094.86) 599.76,1084.62 ccw(c589.51,1094.86) 604,1094.86 ; 604,1094.86 ccw(c618.49,1094.86) 608.24,1084.62 cw(c618.49,1094.86) 604,1094.86
PA1: P2.6 U1.6 | length 1108.4
  Top Layer w8: v1(557,1080.37) 557,1069.37 ; U1.6@606.38,998.11 606.38,1040 584,1062.37 564,1062.37 557,1069.37 ; v1@553.75,1075.33 cw(c549.92,1069.37) 557,1069.37 ; v1@553.75,1075.33 cw(c549.92,1069.37) 557,1069.37 ; v1@553.75,1075.33 cw(c549.92,1069.37) 557,1069.37 ; v1@553.75,1075.33 cw(c549.92,1069.37) 557,1069.37 ; 557,1069.37 cw(c564.08,1069.37) v1@560.25,1075.33 ; 557,1069.37 cw(c564.08,1069.37) v1@560.25,1075.33 ; 557,1069.37 cw(c564.08,1069.37) v1@560.25,1075.33 ; 557,1069.37 cw(c564.08,1069.37) v1@560.25,1075.33
  Bottom Layer w8: P2.6@59,1515.37 P2.6@64,1515.37 208,1515.37 557,1166.37 v1(557,1080.37) ; P2.6@76.39,1502.98 cw(c106.32,1473.06) 106.32,1515.37 cw(c106.32,1557.69) P2.6@76.39,1527.77 ; P2.6@82.05,1497.32 cw(c125.63,1453.75) 125.63,1515.37 cw(c125.63,1577) P2.6@82.05,1533.42 ; 557,1094.86 cw(c542.51,1094.86) 552.76,1084.62 ccw(c542.51,1094.86) 557,1094.86 ; 557,1094.86 ccw(c571.49,1094.86) 561.24,1084.62 cw(c571.49,1094.86) 557,1094.86
PA2: P2.7 U1.7 | length 1055.3
  Top Layer w8: v1(521,1064.37) 521,1051.37 ; U1.7@590.63,998.11 590.63,1022.74 570,1043.37 529,1043.37 521,1051.37 ; v1@517.11,1059.81 cw(c509.92,1051.37) 521,1051.37 ; v1@517.11,1059.81 cw(c509.92,1051.37) 521,1051.37 ; v1@517.11,1059.81 cw(c509.92,1051.37) 521,1051.37 ; v1@517.11,1059.81 cw(c509.92,1051.37) 521,1051.37 ; 521,1051.37 cw(c532.08,1051.37) v1@524.89,1059.81 ; 521,1051.37 cw(c532.08,1051.37) v1@524.89,1059.81 ; 521,1051.37 cw(c532.08,1051.37) v1@524.89,1059.81 ; 521,1051.37 cw(c532.08,1051.37) v1@524.89,1059.81
  Bottom Layer w8: P2.7@59,1415.37 P2.7@64,1415.37 244,1415.37 521,1138.37 v1(521,1064.37) ; P2.7@76.39,1402.98 cw(c106.32,1373.06) 106.32,1415.37 cw(c106.32,1457.69) P2.7@76.39,1427.77 ; P2.7@82.05,1397.32 cw(c125.63,1353.75) 125.63,1415.37 cw(c125.63,1477) P2.7@82.05,1433.42 ; 521,1078.86 cw(c506.51,1078.86) 516.76,1068.62 ccw(c506.51,1078.86) 521,1078.86 ; 521,1078.86 ccw(c535.49,1078.86) 525.24,1068.62 cw(c535.49,1078.86) 521,1078.86
PA3: P2.8 U1.8 | length 985.3
  Top Layer w8: v1(489,1026.37) 562,1026.37 574.88,1013.49 U1.8@574.88,998.11 U1.8@574.88,1008.11 ; 503.49,1026.37 cw(c503.49,1040.86) 493.24,1030.62 ccw(c503.49,1040.86) 503.49,1026.37 ; 503.49,1026.37 ccw(c503.49,1011.89) 493.24,1022.13 cw(c503.49,1011.89) 503.49,1026.37 ; 571.08,1017.3 cw(c561.73,1007.96) 574.94,1007.96 ccw(c561.73,1007.96) 571.08,1017.3
  Bottom Layer w8: P2.8@59,1315.37 P2.8@64,1315.37 275,1315.37 489,1101.37 v1(489,1026.37) ; P2.8@76.39,1302.98 cw(c106.32,1273.06) 106.32,1315.37 cw(c106.32,1357.69) P2.8@76.39,1327.77 ; P2.8@82.05,1297.32 cw(c125.63,1253.75) 125.63,1315.37 cw(c125.63,1377) P2.8@82.05,1333.42 ; 489,1040.86 cw(c474.51,1040.86) 484.76,1030.62 ccw(c474.51,1040.86) 489,1040.86 ; 489,1040.86 ccw(c503.49,1040.86) 493.24,1030.62 cw(c503.49,1040.86) 489,1040.86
